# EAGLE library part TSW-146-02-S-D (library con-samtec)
THROUGH-HOLE .025" SQ POST HEADER Source: Samtec TSW.pdf
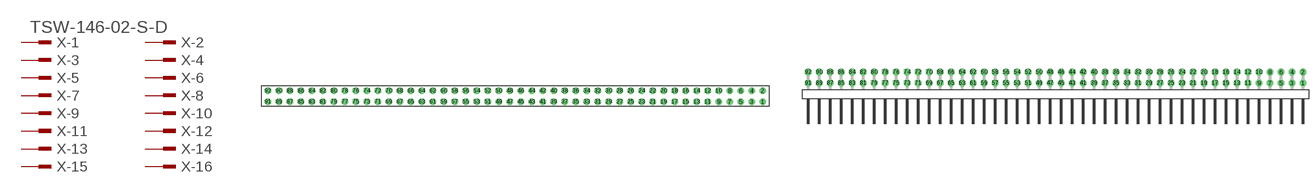
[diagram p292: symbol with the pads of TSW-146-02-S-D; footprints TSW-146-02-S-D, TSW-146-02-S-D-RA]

Designator prefix X; gates -1=MPINV -2=MPIN -3=MPIN -4=MPIN -5=MPIN -6=MPIN -7=MPIN -8=MPIN -9=MPIN -10=MPIN -11=MPIN -12=MPIN -13=MPIN -14=MPIN -15=MPIN -16=MPIN -17=MPIN -18=MPIN -19=MPIN -20=MPIN -21=MPIN -22=MPIN -23=MPIN -24=MPIN -25=MPIN -26=MPIN -27=MPIN -28=MPIN -29=MPIN -30=MPIN -31=MPIN -32=MPIN -33=MPIN -34=MPIN -35=MPIN -36=MPIN -37=MPIN -38=MPIN -39=MPIN -40=MPIN -41=MPIN -42=MPIN -43=MPIN -44=MPIN -45=MPIN -46=MPIN -47=MPIN -48=MPIN -49=MPIN -50=MPIN -51=MPIN -52=MPIN -53=MPIN -54=MPIN -55=MPIN -56=MPIN -57=MPIN -58=MPIN -59=MPIN -60=MPIN -61=MPIN -62=MPIN -63=MPIN -64=MPIN -65=MPIN -66=MPIN -67=MPIN -68=MPIN -69=MPIN -70=MPIN -71=MPIN -72=MPIN -73=MPIN -74=MPIN -75=MPIN -76=MPIN -77=MPIN -78=MPIN -79=MPIN -80=MPIN -81=MPIN -82=MPIN -83=MPIN -84=MPIN -85=MPIN -86=MPIN -87=MPIN -88=MPIN -89=MPIN -90=MPIN -91=MPIN -92=MPIN

## TSW-146-02-S-D (OC_FARNELL: unknown; OC_NEWARK: unknown)  [TSW-146-02-S-D]
1  -1:1  pas
2  -2:1  pas
3  -3:1  pas
4  -4:1  pas
5  -5:1  pas
6  -6:1  pas
7  -7:1  pas
8  -8:1  pas
9  -9:1  pas
10  -10:1  pas
11  -11:1  pas
12  -12:1  pas
13  -13:1  pas
14  -14:1  pas
15  -15:1  pas
16  -16:1  pas
17  -17:1  pas
18  -18:1  pas
19  -19:1  pas
20  -20:1  pas
21  -21:1  pas
22  -22:1  pas
23  -23:1  pas
24  -24:1  pas
25  -25:1  pas
26  -26:1  pas
27  -27:1  pas
28  -28:1  pas
29  -29:1  pas
30  -30:1  pas
31  -31:1  pas
32  -32:1  pas
33  -33:1  pas
34  -34:1  pas
35  -35:1  pas
36  -36:1  pas
37  -37:1  pas
38  -38:1  pas
39  -39:1  pas
40  -40:1  pas
41  -41:1  pas
42  -42:1  pas
43  -43:1  pas
44  -44:1  pas
45  -45:1  pas
46  -46:1  pas
47  -47:1  pas
48  -48:1  pas
49  -49:1  pas
50  -50:1  pas
51  -51:1  pas
52  -52:1  pas
53  -53:1  pas
54  -54:1  pas
55  -55:1  pas
56  -56:1  pas
57  -57:1  pas
58  -58:1  pas
59  -59:1  pas
60  -60:1  pas
61  -61:1  pas
62  -62:1  pas
63  -63:1  pas
64  -64:1  pas
65  -65:1  pas
66  -66:1  pas
67  -67:1  pas
68  -68:1  pas
69  -69:1  pas
70  -70:1  pas
71  -71:1  pas
72  -72:1  pas
73  -73:1  pas
74  -74:1  pas
75  -75:1  pas
76  -76:1  pas
77  -77:1  pas
78  -78:1  pas
79  -79:1  pas
80  -80:1  pas
81  -81:1  pas
82  -82:1  pas
83  -83:1  pas
84  -84:1  pas
85  -85:1  pas
86  -86:1  pas
87  -87:1  pas
88  -88:1  pas
89  -89:1  pas
90  -90:1  pas
91  -91:1  pas
92  -92:1  pas

## TSW-146-02-S-D-RA (OC_FARNELL: unknown; OC_NEWARK: unknown)  [TSW-146-02-S-D-RA]
Pads as for TSW-146-02-S-D

## Footprint TSW-146-02-S-D (pad centres in mm)
THROUGH-HOLE .025" SQ POST HEADER Source: Samtec TSW.pdf
drill 1 pad 1.5 octagon: 1 57.15,-1.27; 2 57.15,1.27; 3 54.61,-1.27; 4 54.61,1.27; 5 52.07,-1.27; 6 52.07,1.27; 7 49.53,-1.27; 8 49.53,1.27; 9 46.99,-1.27; 10 46.99,1.27; 11 44.45,-1.27; 12 44.45,1.27; 13 41.91,-1.27; 14 41.91,1.27; 15 39.37,-1.27; 16 39.37,1.27; 17 36.83,-1.27; 18 36.83,1.27; 19 34.29,-1.27; 20 34.29,1.27; 21 31.75,-1.27; 22 31.75,1.27; 23 29.21,-1.27; 24 29.21,1.27; 25 26.67,-1.27; 26 26.67,1.27; 27 24.13,-1.27; 28 24.13,1.27; 29 21.59,-1.27; 30 21.59,1.27; 31 19.05,-1.27; 32 19.05,1.27; 33 16.51,-1.27; 34 16.51,1.27; 35 13.97,-1.27; 36 13.97,1.27; 37 11.43,-1.27; 38 11.43,1.27; 39 8.89,-1.27; 40 8.89,1.27; 41 6.35,-1.27; 42 6.35,1.27; 43 3.81,-1.27; 44 3.81,1.27; 45 1.27,-1.27; 46 1.27,1.27; 47 -1.27,-1.27; 48 -1.27,1.27; 49 -3.81,-1.27; 50 -3.81,1.27; 51 -6.35,-1.27; 52 -6.35,1.27; 53 -8.89,-1.27; 54 -8.89,1.27; 55 -11.43,-1.27; 56 -11.43,1.27; 57 -13.97,-1.27; 58 -13.97,1.27; 59 -16.51,-1.27; 60 -16.51,1.27; 61 -19.05,-1.27; 62 -19.05,1.27; 63 -21.59,-1.27; 64 -21.59,1.27; 65 -24.13,-1.27; 66 -24.13,1.27; 67 -26.67,-1.27; 68 -26.67,1.27; 69 -29.21,-1.27; 70 -29.21,1.27; 71 -31.75,-1.27; 72 -31.75,1.27; 73 -34.29,-1.27; 74 -34.29,1.27; 75 -36.83,-1.27; 76 -36.83,1.27; 77 -39.37,-1.27; 78 -39.37,1.27; 79 -41.91,-1.27; 80 -41.91,1.27; 81 -44.45,-1.27; 82 -44.45,1.27; 83 -46.99,-1.27; 84 -46.99,1.27; 85 -49.53,-1.27; 86 -49.53,1.27; 87 -52.07,-1.27; 88 -52.07,1.27; 89 -54.61,-1.27; 90 -54.61,1.27; 91 -57.15,-1.27; 92 -57.15,1.27

## Footprint TSW-146-02-S-D-RA (pad centres in mm)
THROUGH-HOLE .025" SQ POST HEADER Source: Samtec TSW.pdf
drill 1 pad 1.5 octagon: 1 57.15,1.524; 2 57.15,4.064; 3 54.61,1.524; 4 54.61,4.064; 5 52.07,1.524; 6 52.07,4.064; 7 49.53,1.524; 8 49.53,4.064; 9 46.99,1.524; 10 46.99,4.064; 11 44.45,1.524; 12 44.45,4.064; 13 41.91,1.524; 14 41.91,4.064; 15 39.37,1.524; 16 39.37,4.064; 17 36.83,1.524; 18 36.83,4.064; 19 34.29,1.524; 20 34.29,4.064; 21 31.75,1.524; 22 31.75,4.064; 23 29.21,1.524; 24 29.21,4.064; 25 26.67,1.524; 26 26.67,4.064; 27 24.13,1.524; 28 24.13,4.064; 29 21.59,1.524; 30 21.59,4.064; 31 19.05,1.524; 32 19.05,4.064; 33 16.51,1.524; 34 16.51,4.064; 35 13.97,1.524; 36 13.97,4.064; 37 11.43,1.524; 38 11.43,4.064; 39 8.89,1.524; 40 8.89,4.064; 41 6.35,1.524; 42 6.35,4.064; 43 3.81,1.524; 44 3.81,4.064; 45 1.27,1.524; 46 1.27,4.064; 47 -1.27,1.524; 48 -1.27,4.064; 49 -3.81,1.524; 50 -3.81,4.064; 51 -6.35,1.524; 52 -6.35,4.064; 53 -8.89,1.524; 54 -8.89,4.064; 55 -11.43,1.524; 56 -11.43,4.064; 57 -13.97,1.524; 58 -13.97,4.064; 59 -16.51,1.524; 60 -16.51,4.064; 61 -19.05,1.524; 62 -19.05,4.064; 63 -21.59,1.524; 64 -21.59,4.064; 65 -24.13,1.524; 66 -24.13,4.064; 67 -26.67,1.524; 68 -26.67,4.064; 69 -29.21,1.524; 70 -29.21,4.064; 71 -31.75,1.524; 72 -31.75,4.064; 73 -34.29,1.524; 74 -34.29,4.064; 75 -36.83,1.524; 76 -36.83,4.064; 77 -39.37,1.524; 78 -39.37,4.064; 79 -41.91,1.524; 80 -41.91,4.064; 81 -44.45,1.524; 82 -44.45,4.064; 83 -46.99,1.524; 84 -46.99,4.064; 85 -49.53,1.524; 86 -49.53,4.064; 87 -52.07,1.524; 88 -52.07,4.064; 89 -54.61,1.524; 90 -54.61,4.064; 91 -57.15,1.524; 92 -57.15,4.064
